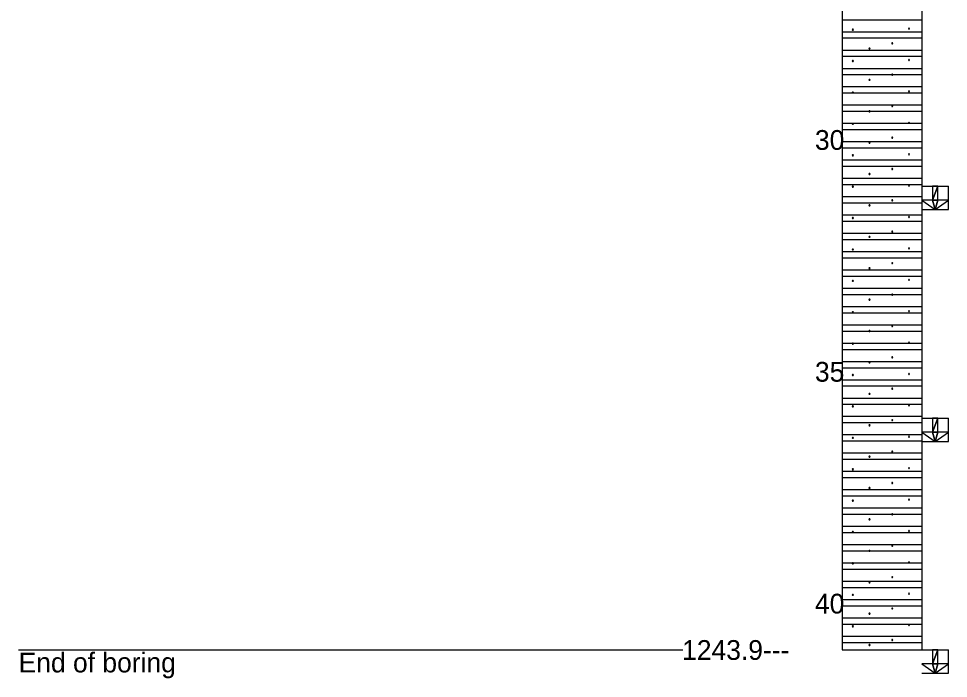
# Model space of a CAD drawing. Extents: x 7 to 126, y 24 to 56.
# Drawn here: x 27.98 to 33.81, y 37.99 to 42.13 of the extents above; entities that cross this region are included whole.
import ezdxf

# ---------------------------------------------------------------- set-up
doc = ezdxf.new("R2010")
doc.units = 0

msp = doc.modelspace()

# ---------------------------------------------------------------- linework, layer by layer
for points in [[(33.1403, 50.0867), (33.1403, 38.1681)], [(33.6403, 50.0867), (33.6403, 38.1681)], [(33.1403, 42.1199), (33.6403, 42.1199)], [(33.2107, 42.0573), (33.2091, 42.0602), (33.2058, 42.0602), (33.2041, 42.0573), (33.2058, 42.0545), (33.2091, 42.0545), (33.2107, 42.0573)], [(33.5635, 42.0638), (33.5618, 42.0667), (33.5585, 42.0667), (33.5569, 42.0638), (33.5585, 42.061), (33.5618, 42.061), (33.5635, 42.0638)], [(33.1403, 42.0445), (33.6403, 42.0445)], [(33.1403, 42.0051), (33.6403, 42.0051)], [(33.3154, 41.9394), (33.3137, 41.9423), (33.3104, 41.9423), (33.3088, 41.9395), (33.3104, 41.9366), (33.3137, 41.9366), (33.3154, 41.9394)], [(33.4579, 41.9713), (33.4563, 41.9741), (33.453, 41.9741), (33.4514, 41.9713), (33.453, 41.9685), (33.4563, 41.9685), (33.4579, 41.9713)], [(33.1403, 41.9296), (33.6403, 41.9296)], [(33.1403, 41.8903), (33.6403, 41.8903)], [(33.1403, 41.8148), (33.6403, 41.8148)], [(33.2107, 41.8605), (33.2091, 41.8633), (33.2058, 41.8633), (33.2041, 41.8605), (33.2058, 41.8576), (33.2091, 41.8576), (33.2107, 41.8605)], [(33.5635, 41.867), (33.5618, 41.8699), (33.5585, 41.8699), (33.5569, 41.867), (33.5585, 41.8642), (33.5618, 41.8642), (33.5635, 41.867)], [(33.1403, 41.7754), (33.6403, 41.7754)], [(33.4579, 41.7745), (33.4563, 41.7773), (33.453, 41.7773), (33.4514, 41.7745), (33.453, 41.7716), (33.4563, 41.7716), (33.4579, 41.7745)], [(33.1403, 41.7), (33.6403, 41.7)], [(33.3154, 41.7426), (33.3137, 41.7455), (33.3104, 41.7455), (33.3088, 41.7426), (33.3104, 41.7398), (33.3137, 41.7398), (33.3154, 41.7426)], [(33.1403, 41.6606), (33.6403, 41.6606)], [(33.2107, 41.6636), (33.2091, 41.6665), (33.2058, 41.6665), (33.2041, 41.6636), (33.2058, 41.6607), (33.2091, 41.6607), (33.2107, 41.6636)], [(33.5635, 41.6701), (33.5618, 41.673), (33.5585, 41.673), (33.5569, 41.6701), (33.5585, 41.6673), (33.5618, 41.6673), (33.5635, 41.6701)], [(33.1403, 41.5852), (33.6403, 41.5852)], [(33.1403, 41.5458), (33.6403, 41.5458)], [(33.3154, 41.5457), (33.3137, 41.5486), (33.3104, 41.5486), (33.3088, 41.5458), (33.3104, 41.5429), (33.3137, 41.5429), (33.3154, 41.5457)], [(33.4579, 41.5776), (33.4563, 41.5804), (33.453, 41.5804), (33.4514, 41.5776), (33.453, 41.5748), (33.4563, 41.5748), (33.4579, 41.5776)], [(33.1403, 41.4703), (33.6403, 41.4703)], [(33.2107, 41.4668), (33.2091, 41.4696), (33.2058, 41.4696), (33.2041, 41.4668), (33.2058, 41.4639), (33.2091, 41.4639), (33.2107, 41.4668)], [(33.5635, 41.4733), (33.5618, 41.4762), (33.5585, 41.4762), (33.5569, 41.4733), (33.5585, 41.4705), (33.5618, 41.4705), (33.5635, 41.4733)], [(33.1403, 41.431), (33.6403, 41.431)], [(33.1403, 41.3555), (33.6403, 41.3555)], [(33.3154, 41.3489), (33.3137, 41.3518), (33.3104, 41.3518), (33.3088, 41.3489), (33.3104, 41.3461), (33.3137, 41.3461), (33.3154, 41.3489)], [(33.4579, 41.3808), (33.4563, 41.3836), (33.453, 41.3836), (33.4514, 41.3808), (33.453, 41.3779), (33.4563, 41.3779), (33.4579, 41.3808)], [(33.1403, 41.3161), (33.6403, 41.3161)], [(33.1403, 41.2407), (33.6403, 41.2407)], [(33.2107, 41.2699), (33.2091, 41.2728), (33.2058, 41.2728), (33.2041, 41.2699), (33.2058, 41.267), (33.2091, 41.267), (33.2107, 41.2699)], [(33.5635, 41.2764), (33.5618, 41.2793), (33.5585, 41.2793), (33.5569, 41.2764), (33.5585, 41.2736), (33.5618, 41.2736), (33.5635, 41.2764)], [(33.1403, 41.2013), (33.6403, 41.2013)], [(33.4579, 41.1839), (33.4563, 41.1867), (33.453, 41.1867), (33.4514, 41.1839), (33.453, 41.1811), (33.4563, 41.1811), (33.4579, 41.1839)], [(33.1403, 41.1258), (33.6403, 41.1258)], [(33.3154, 41.152), (33.3137, 41.1549), (33.3104, 41.1549), (33.3088, 41.1521), (33.3104, 41.1492), (33.3137, 41.1492), (33.3154, 41.152)], [(33.1403, 41.0865), (33.6403, 41.0865)], [(33.2107, 41.0731), (33.2091, 41.0759), (33.2058, 41.0759), (33.2041, 41.0731), (33.2058, 41.0702), (33.2091, 41.0702), (33.2107, 41.0731)], [(33.5635, 41.0796), (33.5618, 41.0825), (33.5585, 41.0825), (33.5569, 41.0796), (33.5585, 41.0768), (33.5618, 41.0768), (33.5635, 41.0796)], [(33.6403, 41.0751), (33.807, 41.0751)], [(33.807, 40.9298), (33.807, 41.0751)], [(33.1403, 41.011), (33.6403, 41.011)], [(33.1403, 40.9716), (33.6403, 40.9716)], [(33.3154, 40.9552), (33.3137, 40.9581), (33.3104, 40.9581), (33.3088, 40.9552), (33.3104, 40.9524), (33.3137, 40.9524), (33.3154, 40.9552)], [(33.4579, 40.9871), (33.4563, 40.9899), (33.453, 40.9899), (33.4514, 40.9871), (33.453, 40.9842), (33.4563, 40.9842), (33.4579, 40.9871)], [(33.1403, 40.8962), (33.6403, 40.8962)], [(33.5635, 40.8827), (33.5618, 40.8856), (33.5585, 40.8856), (33.5569, 40.8827), (33.5585, 40.8799), (33.5618, 40.8799), (33.5635, 40.8827)], [(33.6403, 40.9298), (33.807, 40.9298)], [(33.1403, 40.8568), (33.6403, 40.8568)], [(33.2107, 40.8762), (33.2091, 40.8791), (33.2058, 40.8791), (33.2041, 40.8762), (33.2058, 40.8733), (33.2091, 40.8733), (33.2107, 40.8762)], [(33.1403, 40.7814), (33.6403, 40.7814)], [(33.4579, 40.7902), (33.4563, 40.793), (33.453, 40.793), (33.4514, 40.7902), (33.453, 40.7874), (33.4563, 40.7874), (33.4579, 40.7902)], [(33.1403, 40.742), (33.6403, 40.742)], [(33.3154, 40.7583), (33.3137, 40.7612), (33.3104, 40.7612), (33.3088, 40.7584), (33.3104, 40.7555), (33.3137, 40.7555), (33.3154, 40.7583)], [(33.1403, 40.6665), (33.6403, 40.6665)], [(33.2107, 40.6794), (33.2091, 40.6822), (33.2058, 40.6822), (33.2041, 40.6794), (33.2058, 40.6765), (33.2091, 40.6765), (33.2107, 40.6794)], [(33.5635, 40.6859), (33.5618, 40.6888), (33.5585, 40.6888), (33.5569, 40.6859), (33.5585, 40.6831), (33.5618, 40.6831), (33.5635, 40.6859)], [(33.1403, 40.6272), (33.6403, 40.6272)], [(33.4579, 40.5934), (33.4563, 40.5962), (33.453, 40.5962), (33.4514, 40.5934), (33.453, 40.5905), (33.4563, 40.5905), (33.4579, 40.5934)], [(33.1403, 40.5517), (33.6403, 40.5517)], [(33.3154, 40.5615), (33.3137, 40.5644), (33.3104, 40.5644), (33.3088, 40.5615), (33.3104, 40.5587), (33.3137, 40.5587), (33.3154, 40.5615)], [(33.1403, 40.5123), (33.6403, 40.5123)], [(33.2107, 40.4825), (33.2091, 40.4854), (33.2058, 40.4854), (33.2041, 40.4825), (33.2058, 40.4796), (33.2091, 40.4796), (33.2107, 40.4825)], [(33.5635, 40.489), (33.5618, 40.4919), (33.5585, 40.4919), (33.5569, 40.489), (33.5585, 40.4862), (33.5618, 40.4862), (33.5635, 40.489)], [(33.1403, 40.4369), (33.6403, 40.4369)], [(33.1403, 40.3975), (33.6403, 40.3975)], [(33.3154, 40.3646), (33.3137, 40.3675), (33.3104, 40.3675), (33.3088, 40.3647), (33.3104, 40.3618), (33.3137, 40.3618), (33.3154, 40.3646)], [(33.4579, 40.3965), (33.4563, 40.3993), (33.453, 40.3993), (33.4514, 40.3965), (33.453, 40.3937), (33.4563, 40.3937), (33.4579, 40.3965)], [(33.1403, 40.322), (33.6403, 40.322)], [(33.1403, 40.2827), (33.6403, 40.2827)], [(33.2107, 40.2857), (33.2091, 40.2885), (33.2058, 40.2885), (33.2041, 40.2857), (33.2058, 40.2828), (33.2091, 40.2828), (33.2107, 40.2857)], [(33.5635, 40.2922), (33.5618, 40.2951), (33.5585, 40.2951), (33.5569, 40.2922), (33.5585, 40.2894), (33.5618, 40.2894), (33.5635, 40.2922)], [(33.1403, 40.2072), (33.6403, 40.2072)], [(33.4579, 40.1997), (33.4563, 40.2025), (33.453, 40.2025), (33.4514, 40.1997), (33.453, 40.1968), (33.4563, 40.1968), (33.4579, 40.1997)], [(33.1403, 40.1678), (33.6403, 40.1678)], [(33.3154, 40.1678), (33.3137, 40.1707), (33.3104, 40.1707), (33.3088, 40.1678), (33.3104, 40.1649), (33.3137, 40.1649), (33.3154, 40.1678)], [(33.1403, 40.0924), (33.6403, 40.0924)], [(33.2107, 40.0888), (33.2091, 40.0917), (33.2058, 40.0917), (33.2041, 40.0888), (33.2058, 40.0859), (33.2091, 40.0859), (33.2107, 40.0888)], [(33.5635, 40.0953), (33.5618, 40.0982), (33.5585, 40.0982), (33.5569, 40.0953), (33.5585, 40.0925), (33.5618, 40.0925), (33.5635, 40.0953)], [(33.1403, 40.053), (33.6403, 40.053)], [(33.1403, 39.9775), (33.6403, 39.9775)], [(33.3154, 39.9709), (33.3137, 39.9738), (33.3104, 39.9738), (33.3088, 39.971), (33.3104, 39.9681), (33.3137, 39.9681), (33.3154, 39.9709)], [(33.4579, 40.0028), (33.4563, 40.0056), (33.453, 40.0056), (33.4514, 40.0028), (33.453, 40), (33.4563, 40), (33.4579, 40.0028)], [(33.1403, 39.9382), (33.6403, 39.9382)], [(33.2107, 39.892), (33.2091, 39.8948), (33.2058, 39.8948), (33.2041, 39.892), (33.2058, 39.8891), (33.2091, 39.8891), (33.2107, 39.892)], [(33.5635, 39.8985), (33.5618, 39.9014), (33.5585, 39.9014), (33.5569, 39.8985), (33.5585, 39.8957), (33.5618, 39.8957), (33.5635, 39.8985)], [(33.1403, 39.8627), (33.6403, 39.8627)], [(33.1403, 39.8233), (33.6403, 39.8233)], [(33.3154, 39.7741), (33.3137, 39.777), (33.3104, 39.777), (33.3088, 39.7741), (33.3104, 39.7712), (33.3137, 39.7712), (33.3154, 39.7741)], [(33.4579, 39.806), (33.4563, 39.8088), (33.453, 39.8088), (33.4514, 39.806), (33.453, 39.8031), (33.4563, 39.8031), (33.4579, 39.806)], [(33.1403, 39.7479), (33.6403, 39.7479)], [(33.1403, 39.7085), (33.6403, 39.7085)], [(33.2107, 39.6951), (33.2091, 39.698), (33.2058, 39.698), (33.2041, 39.6951), (33.2058, 39.6922), (33.2091, 39.6922), (33.2107, 39.6951)], [(33.5635, 39.7016), (33.5618, 39.7045), (33.5585, 39.7045), (33.5569, 39.7016), (33.5585, 39.6988), (33.5618, 39.6988), (33.5635, 39.7016)], [(33.1403, 39.6331), (33.6403, 39.6331)], [(33.4579, 39.6091), (33.4563, 39.6119), (33.453, 39.6119), (33.4514, 39.6091), (33.453, 39.6063), (33.4563, 39.6063), (33.4579, 39.6091)], [(33.6403, 39.6216), (33.807, 39.6216)], [(33.807, 39.4763), (33.807, 39.6216)], [(33.1403, 39.5937), (33.6403, 39.5937)], [(33.3154, 39.5772), (33.3137, 39.5801), (33.3104, 39.5801), (33.3088, 39.5773), (33.3104, 39.5744), (33.3137, 39.5744), (33.3154, 39.5772)], [(33.1403, 39.5182), (33.6403, 39.5182)], [(33.2107, 39.4983), (33.2091, 39.5011), (33.2058, 39.5011), (33.2041, 39.4983), (33.2058, 39.4954), (33.2091, 39.4954), (33.2107, 39.4983)], [(33.5635, 39.5048), (33.5618, 39.5077), (33.5585, 39.5077), (33.5569, 39.5048), (33.5585, 39.502), (33.5618, 39.502), (33.5635, 39.5048)], [(33.1403, 39.4789), (33.6403, 39.4789)], [(33.6403, 39.4763), (33.807, 39.4763)], [(33.1403, 39.4034), (33.6403, 39.4034)], [(33.3154, 39.3804), (33.3137, 39.3833), (33.3104, 39.3833), (33.3088, 39.3804), (33.3104, 39.3775), (33.3137, 39.3775), (33.3154, 39.3804)], [(33.4579, 39.4123), (33.4563, 39.4151), (33.453, 39.4151), (33.4514, 39.4123), (33.453, 39.4094), (33.4563, 39.4094), (33.4579, 39.4123)], [(33.1403, 39.364), (33.6403, 39.364)], [(33.5635, 39.3079), (33.5618, 39.3108), (33.5585, 39.3108), (33.5569, 39.3079), (33.5585, 39.3051), (33.5618, 39.3051), (33.5635, 39.3079)], [(33.1403, 39.2886), (33.6403, 39.2886)], [(33.1403, 39.2492), (33.6403, 39.2492)], [(33.2107, 39.3014), (33.2091, 39.3043), (33.2058, 39.3043), (33.2041, 39.3014), (33.2058, 39.2985), (33.2091, 39.2985), (33.2107, 39.3014)], [(33.4579, 39.2154), (33.4563, 39.2182), (33.453, 39.2182), (33.4514, 39.2154), (33.453, 39.2126), (33.4563, 39.2126), (33.4579, 39.2154)], [(33.1403, 39.1737), (33.6403, 39.1737)], [(33.1403, 39.1344), (33.6403, 39.1344)], [(33.3154, 39.1835), (33.3137, 39.1864), (33.3104, 39.1864), (33.3088, 39.1836), (33.3104, 39.1807), (33.3137, 39.1807), (33.3154, 39.1835)], [(33.2107, 39.1046), (33.2091, 39.1074), (33.2058, 39.1074), (33.2041, 39.1046), (33.2058, 39.1017), (33.2091, 39.1017), (33.2107, 39.1046)], [(33.5635, 39.1111), (33.5618, 39.114), (33.5585, 39.114), (33.5569, 39.1111), (33.5585, 39.1083), (33.5618, 39.1083), (33.5635, 39.1111)], [(33.1403, 39.0589), (33.6403, 39.0589)], [(33.1403, 39.0195), (33.6403, 39.0195)], [(33.4579, 39.0186), (33.4563, 39.0214), (33.453, 39.0214), (33.4514, 39.0186), (33.453, 39.0157), (33.4563, 39.0157), (33.4579, 39.0186)], [(33.3154, 38.9867), (33.3137, 38.9896), (33.3104, 38.9896), (33.3088, 38.9867), (33.3104, 38.9838), (33.3137, 38.9838), (33.3154, 38.9867)], [(33.1403, 38.9441), (33.6403, 38.9441)], [(33.1403, 38.9047), (33.6403, 38.9047)], [(33.2107, 38.9077), (33.2091, 38.9106), (33.2058, 38.9106), (33.2041, 38.9077), (33.2058, 38.9048), (33.2091, 38.9048), (33.2107, 38.9077)], [(33.5635, 38.9142), (33.5618, 38.9171), (33.5585, 38.9171), (33.5569, 38.9142), (33.5585, 38.9114), (33.5618, 38.9114), (33.5635, 38.9142)], [(33.1403, 38.8293), (33.6403, 38.8293)], [(33.1403, 38.7899), (33.6403, 38.7899)], [(33.3154, 38.7898), (33.3137, 38.7927), (33.3104, 38.7927), (33.3088, 38.7899), (33.3104, 38.787), (33.3137, 38.787), (33.3154, 38.7898)], [(33.4579, 38.8217), (33.4563, 38.8245), (33.453, 38.8245), (33.4514, 38.8217), (33.453, 38.8189), (33.4563, 38.8189), (33.4579, 38.8217)], [(33.1403, 38.7144), (33.6403, 38.7144)], [(33.1403, 38.6751), (33.6403, 38.6751)], [(33.2107, 38.7109), (33.2091, 38.7137), (33.2058, 38.7137), (33.2041, 38.7109), (33.2058, 38.708), (33.2091, 38.708), (33.2107, 38.7109)], [(33.5635, 38.7174), (33.5618, 38.7203), (33.5585, 38.7203), (33.5569, 38.7174), (33.5585, 38.7146), (33.5618, 38.7146), (33.5635, 38.7174)], [(33.4579, 38.6249), (33.4563, 38.6277), (33.453, 38.6277), (33.4514, 38.6249), (33.453, 38.622), (33.4563, 38.622), (33.4579, 38.6249)], [(33.1403, 38.5996), (33.6403, 38.5996)], [(33.1403, 38.5602), (33.6403, 38.5602)], [(33.3154, 38.593), (33.3137, 38.5959), (33.3104, 38.5959), (33.3088, 38.593), (33.3104, 38.5901), (33.3137, 38.5901), (33.3154, 38.593)], [(33.2107, 38.514), (33.2091, 38.5169), (33.2058, 38.5169), (33.2041, 38.514), (33.2058, 38.5111), (33.2091, 38.5111), (33.2107, 38.514)], [(33.5635, 38.5205), (33.5618, 38.5234), (33.5585, 38.5234), (33.5569, 38.5205), (33.5585, 38.5177), (33.5618, 38.5177), (33.5635, 38.5205)], [(33.1403, 38.4848), (33.6403, 38.4848)], [(33.1403, 38.4454), (33.6403, 38.4454)], [(33.3154, 38.3961), (33.3137, 38.399), (33.3104, 38.399), (33.3088, 38.3962), (33.3104, 38.3933), (33.3137, 38.3933), (33.3154, 38.3961)], [(33.4579, 38.428), (33.4563, 38.4308), (33.453, 38.4308), (33.4514, 38.428), (33.453, 38.4252), (33.4563, 38.4252), (33.4579, 38.428)], [(33.1403, 38.3699), (33.6403, 38.3699)], [(33.1403, 38.3306), (33.6403, 38.3306)], [(33.2107, 38.3172), (33.2091, 38.32), (33.2058, 38.32), (33.2041, 38.3172), (33.2058, 38.3143), (33.2091, 38.3143), (33.2107, 38.3172)], [(33.5635, 38.3237), (33.5618, 38.3266), (33.5585, 38.3266), (33.5569, 38.3237), (33.5585, 38.3209), (33.5618, 38.3209), (33.5635, 38.3237)], [(33.1403, 38.2551), (33.6403, 38.2551)], [(33.1403, 38.2157), (33.6403, 38.2157)], [(33.3154, 38.1993), (33.3137, 38.2022), (33.3104, 38.2022), (33.3088, 38.1993), (33.3104, 38.1964), (33.3137, 38.1964), (33.3154, 38.1993)], [(33.4579, 38.2312), (33.4563, 38.234), (33.453, 38.234), (33.4514, 38.2312), (33.453, 38.2283), (33.4563, 38.2283), (33.4579, 38.2312)], [(27.9751, 38.1681), (32.1417, 38.1681)], [(33.1403, 38.1681), (33.6403, 38.1681)], [(33.6403, 38.1681), (33.807, 38.1681)], [(33.807, 38.0228), (33.807, 38.1681)], [(33.6403, 38.0228), (33.807, 38.0228)]]:
    msp.add_lwpolyline(points)
for points in [[(33.707, 40.9879), (33.7403, 40.9879), (33.7403, 41.0751), (33.707, 40.9879)], [(33.707, 40.9879), (33.7403, 41.0751), (33.707, 41.0751), (33.707, 40.9879)], [(33.707, 40.9879), (33.6403, 40.9879), (33.7236, 40.9298), (33.707, 40.9879)], [(33.707, 40.9879), (33.7236, 40.9298), (33.7403, 40.9879), (33.707, 40.9879)], [(33.7236, 40.9298), (33.807, 40.9879), (33.7403, 40.9879), (33.7236, 40.9298)], [(33.707, 39.5344), (33.7403, 39.5344), (33.7403, 39.6216), (33.707, 39.5344)], [(33.707, 39.5344), (33.7403, 39.6216), (33.707, 39.6216), (33.707, 39.5344)], [(33.707, 39.5344), (33.6403, 39.5344), (33.7236, 39.4763), (33.707, 39.5344)], [(33.707, 39.5344), (33.7236, 39.4763), (33.7403, 39.5344), (33.707, 39.5344)], [(33.7236, 39.4763), (33.807, 39.5344), (33.7403, 39.5344), (33.7236, 39.4763)], [(33.707, 38.0809), (33.7403, 38.0809), (33.7403, 38.1681), (33.707, 38.0809)], [(33.707, 38.0809), (33.7403, 38.1681), (33.707, 38.1681), (33.707, 38.0809)], [(33.707, 38.0809), (33.6403, 38.0809), (33.7236, 38.0228), (33.707, 38.0809)], [(33.707, 38.0809), (33.7236, 38.0228), (33.7403, 38.0809), (33.707, 38.0809)], [(33.7236, 38.0228), (33.807, 38.0809), (33.7403, 38.0809), (33.7236, 38.0228)]]:
    msp.add_lwpolyline(points, close=True)

# ---------------------------------------------------------------- texts
for s, p in [('30', (32.9699, 41.3038)), ('35', (32.9699, 39.8503)), ('40', (32.9699, 38.3968)), ('1243.9---', (32.1368, 38.1061)), ('End of boring', (27.9751, 38.0275))]:
    msp.add_text(s, height=0.124).set_placement(p)

doc.saveas('drawing.dxf')
